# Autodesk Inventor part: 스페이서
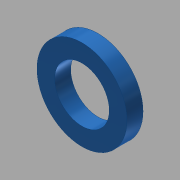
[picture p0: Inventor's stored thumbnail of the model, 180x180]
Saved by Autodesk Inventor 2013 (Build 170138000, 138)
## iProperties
Created: 2018-01
Part Number: 스페이서
Material: 스테인리스강
Document SubType Name: Modeling
Designer: mduedu
Density: 8.08 g/cm^3
Mass: 1.9633 g
Surface Area: 3.71101 cm^2
Volume: 0.242983 cm^3
Author: mduedu
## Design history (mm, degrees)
sketch "스케치1"
  geometry: C1 r 7 at (0, 0); C2 r 4.25 at (0, 0); 1 further point
  constraints: 2 centre point, 2 coincident
  dimensions: "d0" = 14 diameter of C1; "d1" = 8.5 diameter of C2
extrude "돌출1" new body sketch "스케치1" distance "d2" = 2.5; taper "d3" = 0 deg
node "솔리드1"
